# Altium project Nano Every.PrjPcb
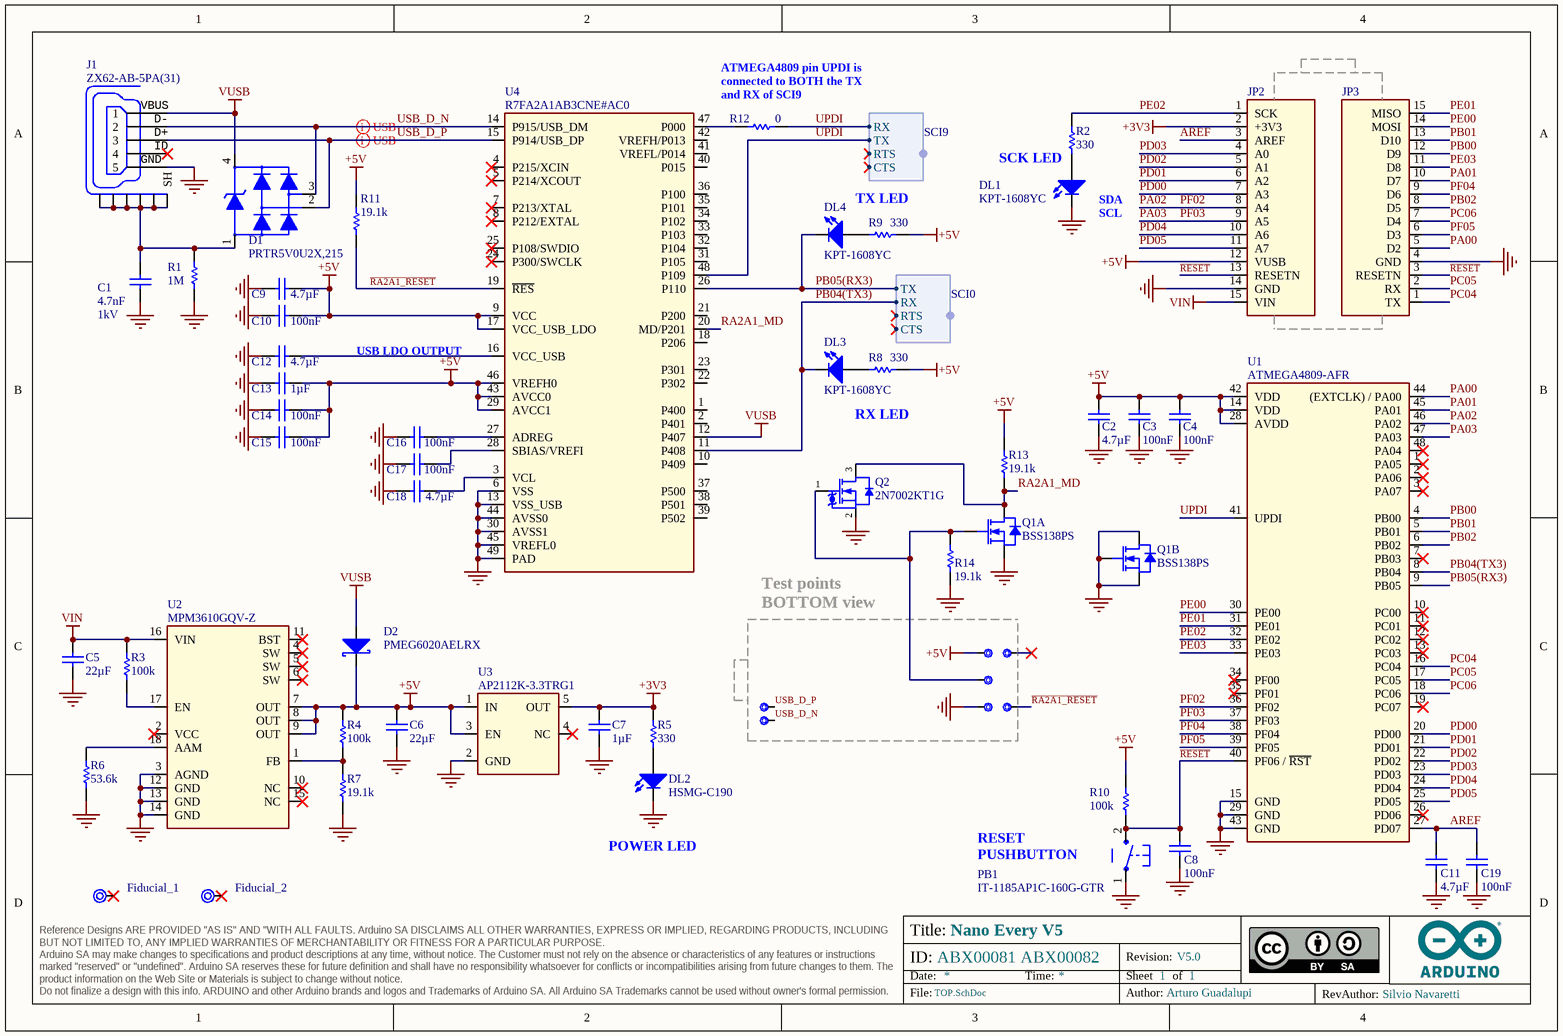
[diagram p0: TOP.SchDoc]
ASSEMBLY_BGA: _; ASSEMBLY_PRESSFIT: _; ASSEMBLY_SMD: X; ASSEMBLY_THT: _; BOARD_INFO_AUTHOR: Silvio Navaretti; BOARD_INFO_Er: _; BOARD_INFO_FLEX: _; BOARD_INFO_FR4: X; BOARD_INFO_FR4_HTG: _; BOARD_INFO_IPC1: _; BOARD_INFO_IPC2: _; BOARD_INFO_IPC3: _; BOARD_INFO_IPC_NA: X; BOARD_INFO_NUMBER_OF_LAYERS: 4; BOARD_INFO_PCB_SIZE: _; BOARD_INFO_POLYMIDE: _; BOARD_INFO_RIGID: X; BOARD_INFO_RIGID/FLEX: _; BOARD_INFO_TBD: _; BOARD_INFO_THICKNESS: 1.6mm; DRILLS_BLIND: _; DRILLS_BURIED: _; DRILLS_COPPER_FILLING: _; DRILLS_FULL: X; DRILLS_LASER: _; DRILLS_PRESSFIT: _; DRILLS_RESIN_FILLING: _; DRILLS_SLOT: _; DRILLS_SOLDER_FILLING: X; FINISH_ADJUSTMENTS: _; FINISH_EDGE_PLATING: _; FINISH_ENIG: X; FINISH_HAL: _; FINISH_HAL_LF: _; FINISH_NI/AU: _; FINISH_SILK_BOTTOM: X; FINISH_SILK_COLOR: WHITE; FINISH_SILK_TOP: X; FINISH_SN/PB: _; FINISH_SOLDERMASK_BOTTOM: X; FINISH_SOLDERMASK_COLOR: BLUE; FINISH_SOLDERMASK_PEELABLE_BOTTOM: _; FINISH_SOLDERMASK_PEELABLE_COLOR: _; FINISH_SOLDERMASK_PEELABLE_TOP: _; FINISH_SOLDERMASK_TOP: X; FINISH_TABS: _; FINISH_TBD: _; INSULATION_MIN_INNER: 0.15mm; INSULATION_MIN_OUTER: 0.15mm; PANEL_MILLING: X; PANEL_NOT_REQUESTED: _; PANEL_NUMBER_OF_FIGURES: 28; PANEL_PROVIDED: X; PANEL_REQUESTED: _; PANEL_SCORING: X; PANEL_SIZE: 211mm x 180.46mm; PANEL_TABS: _; Revision: V5.0; SKU: ABX00081 ABX00082; TRACK_MIN_WIDTH_INNER: 0.15mm; TRACK_MIN_WIDTH_OUTER: 0.15mm; VIA_1: _; VIA_1_HOLE_MM: _; VIA_1_PAD_MM: _; VIA_2: _; VIA_2_HOLE_MM: _; VIA_2_PAD_MM: _; VIA_3: _; VIA_3_HOLE_MM: _; VIA_3_PAD_MM: _; VIA_4: _; VIA_4_HOLE_MM: _; VIA_4_PAD_MM: _; VIA_5: _; VIA_5_HOLE_MM: _; VIA_5_PAD_MM: _; VIA_THROUGH: X; VIA_THROUGH_HOLE_MM: 0.3; VIA_THROUGH_PAD_MM: 0.6
1 sheet, 58 parts. Net scope: hierarchical (ports join the sheet entries above them; power ports are global).
Board files: PCB.PcbDoc, PANEL.PcbDoc

## Sheet TOP.SchDoc: Nano Every V5
size A4; Author: Arturo Guadalupi; DocumentNumber: ABX00081 ABX00082; Revision: V5.0; SheetNumber: 1; SheetTotal: 1; RevAuthor: Silvio Navaretti

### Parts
C1  value 4.7nF  Voltage: 1kV  [CAP-0805]  (hidden comment: FV21X472K102ECG)
C2  value 4.7µF  [CAP-0603]  (hidden comment: GRM188R61C475KAAJD)
C3  value 100nF  [CAP-0402]  (hidden comment: GRM155R61H104KE19D)
C4  value 100nF  [CAP-0402]  (hidden comment: GRM155R61H104KE19D)
C5  value 22µF  [CAP-0805]  (hidden comment: CL21A226MAQNNNE)
C6  value 22µF  [CAP-0805]  (hidden comment: CL21A226MAQNNNE)
C7  value 1µF  [CAP-0402]  (hidden comment: CL05A105KP5NNNC)
C8  value 100nF  [CAP-0402]  (hidden comment: GRM155R61H104KE19D)
C9  value 4.7µF  [CAP-0603]  (hidden comment: GRM188R61C475KAAJD)
C10  value 100nF  [CAP-0402]  (hidden comment: GRM155R61H104KE19D)
C11  value 4.7µF  [CAP-0603]  (hidden comment: GRM188R61C475KAAJD)
C12  value 4.7µF  [CAP-0603]  (hidden comment: GRM188R61C475KAAJD)
C13  value 1µF  [CAP-0402]  (hidden comment: CL05A105KP5NNNC)
C14  value 100nF  [CAP-0402]  (hidden comment: GRM155R61H104KE19D)
C15  value 100nF  [CAP-0402]  (hidden comment: GRM155R61H104KE19D)
C16  value 100nF  [CAP-0402]  (hidden comment: GRM155R61H104KE19D)
C17  value 100nF  [CAP-0402]  (hidden comment: GRM155R61H104KE19D)
C18  value 4.7µF  [CAP-0603]  (hidden comment: GRM188R61C475KAAJD)
C19  value 100nF  [CAP-0402]  (hidden comment: GRM155R61H104KE19D)
D1  PRTR5V0U2X,215  [SOT190P230X110-4N]
D2  PMEG6020AELRX  [SOD123-1]
D+  CMP-018-0005-A.3  [TP-1.00MM]  (value not drawn)  (no BOM)
D-  CMP-018-0005-A.3  [TP-1.00MM]  (value not drawn)  (no BOM)
DL1  KPT-1608YC  [LEDC1608X80N-AK]
DL2  HSMG-C190  [LEDC1608X80N-AK]
DL3  KPT-1608YC  [LEDC1608X80N-AK]
DL4  KPT-1608YC  [LEDC1608X80N-AK]
Fiducial_1  Fiducial mark 1mm with 2mm solder  [Fiducial mark 1mm with circle-Footprint-1]  (value not drawn)  (no BOM)
Fiducial_2  Fiducial mark 1mm with 2mm solder  [Fiducial mark 1mm with circle-Footprint-1]  (value not drawn)  (no BOM)
J1  ZX62-AB-5PA(31)  [ZX62-AB-5PA]
JP2  PINHD-1X15-NANO-ANALOG-CASTELLATED  [PINHD-1X14_5VF]  (value not drawn)
JP3  PINHD-1X15-NANO-DIGITAL-CASTELLATED  [PINHD-1X14_5VF]  (value not drawn)
PB1  IT-1185AP1C-160G-GTR  [C&K_PTS820_NO_HOLES-1]
Q1  BSS138PS  [SOT363]  (parts A,B of 2)
Q2  2N7002KT1G  [SOT23]
R1  value 1M  [RES-0402]  (hidden comment: CRCW04021M00FKED)
R2  value 330  [RES-0402]  (hidden comment: CRCW0402330RJNED)
R3  value 100k  [RES-0402]  (hidden comment: CRCW0402100KFKEDC)
R4  value 100k  [RES-0402]  (hidden comment: CRCW0402100KFKEDC)
R5  value 330  [RES-0402]  (hidden comment: CRCW0402330RJNED)
R6  value 53.6k  [RES-0402]  (hidden comment: CRCW040253K6FKED)
R7  value 19.1k  [RES-0402]  (hidden comment: CRCW040219K1FKEDC)
R8  value 330  [RES-0402]  (hidden comment: CRCW0402330RJNED)
R9  value 330  [RES-0402]  (hidden comment: CRCW0402330RJNED)
R10  value 100k  [RES-0402]  (hidden comment: CRCW0402100KFKEDC)
R11  value 19.1k  [RES-0402]  (hidden comment: CRCW040219K1FKEDC)
R12  value 0  [RES-0402]  (hidden comment: CRCW04020000Z0EDC)
R13  value 19.1k  [RES-0402]  (hidden comment: CRCW040219K1FKEDC)
R14  value 19.1k  [RES-0402]  (hidden comment: CRCW040219K1FKEDC)
TP_5V  CMP-018-0005-A.3  [TP-1.00MM]  (value not drawn)  (no BOM)
TP_GND  CMP-018-0005-A.3  [TP-1.00MM]  (value not drawn)  (no BOM)
TP_MD  CMP-018-0005-A.3  [TP-1.00MM]  (value not drawn)  (no BOM)
TP_RESETN  CMP-018-0005-A.3  [TP-1.00MM]  (value not drawn)  (no BOM)
TP_SWDIO  CMP-018-0005-A.3  [TP-1.00MM]  (value not drawn)  (no BOM)
U1  ATMEGA4809-AFR  [CQFP50P900X900X120-48N]
U2  MPM3610GQV-Z  [POWER-LQFN20]
U3  AP2112K-3.3TRG1  [SOT25]
U4  R7FA2A1AB3CNE#AC0  [QFN127P600-8N]

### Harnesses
SCI0: RX, TX, RTS, CTS
SCI9: RX, TX, RTS, CTS

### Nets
+3V3: C7.2 JP2.2(+3V3) R5.2 U3.5(OUT)
+5V: C2.2 C3.2 C4.2 C6.2 C9.2 C10.2 C13.2 C14.2 C15.2 D2.C JP2.12(VUSB) R4.2 R8.2 R9.2 R10.2 R11.2 R13.2 TP_5V.X U1.14(VDD) U1.28(AVDD) U1.42(VDD) U2.7(OUT) U2.8(OUT) U2.9(OUT) U3.1(IN) U3.3(EN) U4.9(VCC) U4.17(VCC_USB_LDO) U4.29(AVCC1) U4.43(AVCC0) U4.46(VREFH0)
GND: C1.1 C2.1 C3.1 C4.1 C5.1 C6.1 C7.1 C8.1 C9.1 C10.1 C11.1 C12.1 C13.1 C14.1 C15.1 C16.1 C17.1 C18.1 C19.1 DL1.C DL2.C J1.5 JP2.14(GND) JP3.4(GND) PB1.1 Q1.1(S) Q1.3(D) Q1.4(S) Q1.5(G) Q2.2(S) R1.1 R6.1 R7.1 R14.1 TP_GND.X U1.15(GND) U1.29(GND) U1.43(GND) U2.3(AGND) U2.12(GND) U2.13(GND) U2.14(GND) U3.2(GND) U4.6(VSS) U4.13(VSS_USB) U4.30(AVSS1) U4.44(AVSS0) U4.45(VREFL0) U4.49(PAD)
VIN: C5.2 JP2.15(VIN) R3.2 U2.16(VIN)
VUSB: D1.4 D2.A J1.1 U4.12(P407)
AREF: C11.2 C19.2 JP2.3(AREF) U1.27(PD07)  [project net AREF_1]
PA00: JP3.5(D2) U1.44((EXTCLK)_/_PA00)  [project net PA00_1]
PA01: JP3.10(D7) U1.45(PA01)  [project net PA01_1]
PA02: JP2.8(A4) U1.36(PF02) U1.46(PA02)  [also labelled PF02]  [project net PA02_1]
PA03: JP2.9(A5) U1.37(PF03) U1.47(PA03)  [also labelled PF03]  [project net PA03_1]
PB00: JP3.12(D9) U1.4(PB00)  [project net PB00_1]
PB01: JP3.13(D10) U1.5(PB01)  [project net PB01_1]
PB02: JP3.8(D5) U1.6(PB02)  [project net PB02_1]
PB04(TX3): DL3.C U1.8(PB04) U4.11(P408) ; harness SCI0.RX
PB05(RX3): DL4.C U1.9(PB05) U4.26(P110) ; harness SCI0.TX
PC04: JP3.1(TX) U1.16(PC04)  [project net PC04_1]
PC05: JP3.2(RX) U1.17(PC05)  [project net PC05_1]
PC06: JP3.7(D4) U1.18(PC06)  [project net PC06_1]
PD00: JP2.7(A3) U1.20(PD00)  [project net PD00_1]
PD01: JP2.6(A2) U1.21(PD01)  [project net PD01_1]
PD02: JP2.5(A1) U1.22(PD02)  [project net PD02_1]
PD03: JP2.4(A0) U1.23(PD03)  [project net PD03_1]
PD04: JP2.10(A6) U1.24(PD04)  [project net PD04_1]
PD05: JP2.11(A7) U1.25(PD05)  [project net PD05_1]
PE00: JP3.14(MOSI) U1.30(PE00)  [project net PE00_1]
PE01: JP3.15(MISO) U1.31(PE01)  [project net PE01_1]
PE02: JP2.1(SCK) R2.2 U1.32(PE02)  [project net PE02_1]
PE03: JP3.11(D8) U1.33(PE03)  [project net PE03_1]
PF04: JP3.9(D6) U1.38(PF04)  [project net PF04_1]
PF05: JP3.6(D3) U1.39(PF05)  [project net PF05_1]
~{RA2A1_RESET}: R11.1 TP_RESETN.X U4.19(~{RES})  [project net ~{RA2A1_RESET}_1]
~{RESET}: C8.2 JP2.13(RESETN) JP3.3(RESETN) PB1.2 R10.1 U1.40(PF06_/_~{RST})  [project net ~{RESET}_1]
RA2A1_MD: Q1.6(D) Q2.3(D) R13.1 U4.20(MD/P201)  [project net RA2A1_MD_1]
UPDI: R12.2 U1.41(UPDI) U4.48(P109) ; harness SCI9.RX, harness SCI9.TX
USB_D_N: D1.3 D-.X J1.2 U4.14(P915/USB_DM)  [project net USB_D_N_1]
USB_D_P: D1.2 D+.X J1.3 U4.15(P914/USB_DP)  [project net USB_D_P_1]
NetC1_2: C1.2 D1.1 J1.M1(SH) J1.M2(SH) J1.M3(SH) J1.M4(SH) J1.M5(SH) J1.M6(SH) R1.2
NetC12_2: C12.2 U4.16(VCC_USB)
NetC16_2: C16.2 U4.27(ADREG)
NetC17_2: C17.2 U4.28(SBIAS/VREFI)
NetC18_2: C18.2 U4.3(VCL)
NetDL1_A: DL1.A R2.1
NetDL2_A: DL2.A R5.1
NetDL3_A: DL3.A R8.1
NetDL4_A: DL4.A R9.1
NetQ1_2: Q1.2(G) Q2.1(G) R14.2 TP_MD.X
NetR3_1: R3.1 U2.17(EN)
NetR4_1: R4.1 R7.2 U2.1(FB)
NetR6_2: R6.2 U2.18(AAM)
NetR12_1: R12.1 U4.47(P000)

Not connected (* = marked no-connect by the designer): Fiducial_1 1*; Fiducial_2 1*; J1 4*; TP_SWDIO X*; U1 1(PA05)* 2(PA06)* 3(PA07)* 7(PB03)* 10(PC00)* 11(PC01)* 12(PC02)* 13(PC03)* 19(PC07)* 26(PD06)* 34(PF00)* 35(PF01)* 48(PA04)*; U2 2(VCC)* 4(SW)* 5(SW)* 6(SW)* 10(NC)* 11(BST)* 15(NC)*; U3 4(NC)*; U4 1(P400) 2(P401) 4(P215/XCIN)* 5(P214/XCOUT)* 7(P213/XTAL)* 8(P212/EXTAL)* 10(P409) 18(P206) 21(P200) 22(P302) 23(P301) 24(P300/SWCLK)* 25(P108/SWDIO)* 31(P105) 32(P104) 33(P103) 34(P102) 35(P101) 36(P100) 37(P500) 38(P501) 39(P502) 40(P015) 41(VREFL/P014) 42(VREFH/P013)

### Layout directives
differential pair; differential pair class USB: USB_D_N_1, USB_D_P_1

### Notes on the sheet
- ATMEGA4809 pin UPDI is connected to BOTH the TX and RX of SCI9
- SCK LED
- TX LED
- (near DL1) SDA
- (near DL1) SCL
- (near U4) USB LDO OUTPUT
- RX LED
- Test points BOTTOM view
- (near DL2) POWER LED
- RESET
  PUSHBUTTON

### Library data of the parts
C1 = C0059-A.14: CAP CHIP 0805 4.7nF 10% 1000V X7R; Manufacturer: PSA Shenzen; Code Arduino: 0689
C2 C9 C11 C12 C18 = C0054-A.16: CAP CHIP 0603 4.7uF 10% 16V X5R; Manufacturer: Murata; Code Arduino: A5072
C3 C4 C8 C10 C14-C17 C19 = C0015-A.14: CAP CHIP 0402 100nF 10% 50V X5R; Manufacturer: Murata; Code Arduino: A5141
C5 C6 = C0111-A.7: CAP CHIP 0805 22uF 20% 25V X5R; Manufacturer: Samsung Electro-Mechanics; Code Arduino: C0111
C7 C13 = C0017-A.14: CAP CHIP 0402 1uF 10% 10V X5R; Manufacturer: Samsung Electro-Mechanics; Code Arduino: 0133
D1 = D0025-A.5: TVS ARRAY 4LIN.8kV 1pF SOT143B; Manufacturer: Nexperia; Device Type: ESD protection; Code Arduino: 2209
D2 = D0026-A.6: DIODE SCHOTTKY SMD 2A 60V SOD123FL; Manufacturer: Nexperia; Manucturer Part Number 2: SS26L; Code Arduino: 2208; Forward Voltage: 0.6V; Manucturer 2: Hottech
D+ D- TP_5V TP_GND TP_MD TP_RESETN TP_SWDIO = UT0013-A.4: Test point 1.00mm
DL1 DL3 DL4 = L0008-A.5: LED SMD 0603 GIA588   8mcd 120^; Manufacturer: Kingbright; Code Arduino: 2243
DL2 = L0009-A.5: LED SMD 0603 GREEN/568 15mcd 120^; Manufacturer: Broadcom; Code Arduino: 2204
Fiducial_1 Fiducial_2 = UT0024-A.6
J1 = J0039-A.7: CONN USB MICRO F/90^ SMD TipoAB 5x1; Manufacturer: Hirose; Code Arduino: 2219
JP2 = J0158-A.4: CONN THD SOCKET F/1/D 15V JANALOG NANO-TYPE CASTELLATED; Code Arduino: 0646
JP3 = J0183-A.4: CONN THD SOCKET F/1/D 15V JDIGITAL NANO-TYPE CASTELLATED; Code Arduino: 0646
PB1 = B0001-A.7: PUSHBUTTON WHITE NO ANCHORS; Manufacturer: Switronic; Code Arduino: 0173
Q1 = T0012-A.8: MOSFET N-CH 2x 60V 0.32A SOT363; Manufacturer: Nexperia; Device Type: Mosfet 2N-CH SMD; Code Arduino: 2323
Q2 = T0004-A.9: MOSFET N-CH 60V 300mA ESD prot. SOT23; Manufacturer: On Semiconductor; Device Type: Mosfet N-CH SMD; Code Arduino: A5393
R1 = R0058-A.24: RES CHIP 0402 1M 1% 1/16W; Manufacturer: Vishay; Power: 62.5mW; Code Arduino: 0139; Temperature coefficient: 100ppm
R2 R5 R8 R9 = R0017-A.24: RES CHIP 0402 330R 5% 1/16W; Manufacturer: Vishay; Code Arduino: 2229; Power: 62.5mW; Temperature coefficient: 200ppm
R3 R4 R10 = R0001-A.24: RES CHIP 0402 100k 1% 1/16W; Manufacturer: Vishay; Code Arduino: 0134; Power: 62.5mW; Temperature coefficient: 100ppm
R6 = R0050-A.24: RES CHIP 0402 53k6 1% 1/16W; Manufacturer: Vishay; Code Arduino: A5313; Power: 62.5mW; Temperature coefficient: 100ppm
R7 R11 R13 R14 = R0033-A.24: RES CHIP 0402 19k1 1% 1/16W; Manufacturer: Vishay; Power: 62.5mW; Code Arduino: A5369; Temperature coefficient: 100ppm
R12 = R0000-A.24: RES CHIP 0402 0R 1/16W; Manufacturer: Vishay; Code Arduino: 0039; Power: 62.5mW; Tolerance: 0%; Temperature coefficient: 0ppm
U1 = U0039-A.7: Manufacturer: Microchip
U2 = U0075-A.13: IC Buck with integrated inductor 4.5 to 21V max 1.2A QFN20 3x5x1.6mm; Manufacturer: MPS; Code Arduino: 2093
U3 = U0027-A.11: IC LDO Vin max 6.5V Vout 3V3 Iout 600mA +EN  SOT25; Manufacturer: Diodes Inc; Code Arduino: 2199
U4 = U0258-A.7: IC uC 32b 256k +8k flash 32k RAM 1V8 to 5.5V QFN48; Manufacturer: Renesas; Code Arduino: U0258

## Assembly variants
ABX00081: not fitted Fiducial_1 Fiducial_2 JP2 JP3 Q2
ABX00082: not fitted Fiducial_1 Fiducial_2 Q2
